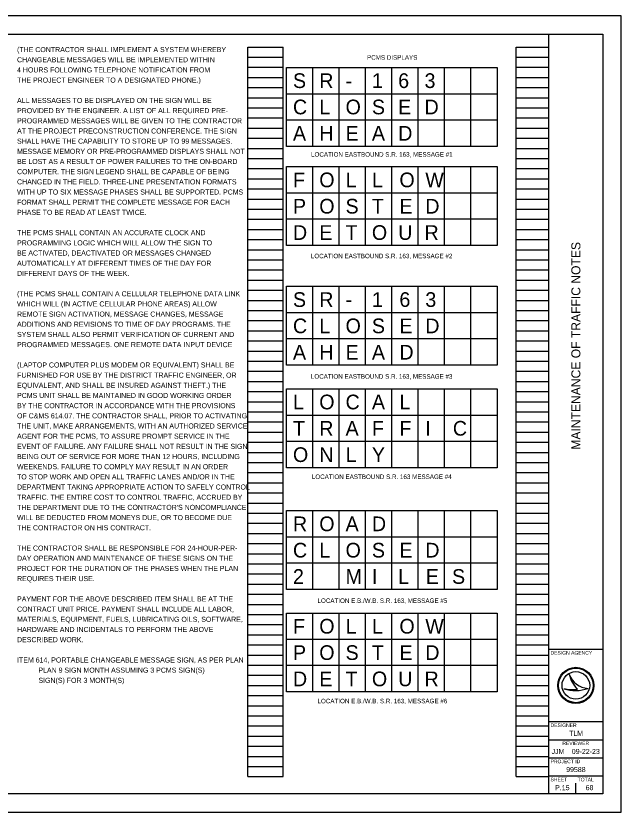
# Model space of a CAD drawing. Extents: x 0 to 34, y 0 to 22.
# Drawn here: x 17.27 to 34, y 0 to 22 of the extents above; entities that cross this region are included whole.
import ezdxf

# ---------------------------------------------------------------- set-up
doc = ezdxf.new("R2010")
doc.units = 0
for name, color, linetype in [('SH_Border', 7, 'Continuous'), ('SH_Cut_Line', 7, 'Continuous'), ('SH_Data', 7, 'Continuous'), ('SH_Text', 7, 'Continuous')]:
    doc.layers.add(name, color=color, linetype=linetype)

msp = doc.modelspace()

# ---------------------------------------------------------------- linework, layer by layer
at = {"layer": 'SH_Border'}
for p, q in [((32, 0.5), (32, 21.5)), ((32, 4.5), (33.5, 4.5)), ((32, 2.5), (33.5, 2.5)), ((32, 2), (33.5, 2)), ((32, 1.5), (33.5, 1.5)), ((32, 1), (33.5, 1))]:
    msp.add_line(p, q, dxfattribs=at)
msp.add_lwpolyline([(1.5, 21.5), (33.5, 21.5), (33.5, 0.5), (1.5, 0.5)], close=True, dxfattribs=at)
at = {"layer": 'SH_Cut_Line'}
msp.add_lwpolyline([(0, 0), (34, 0), (34, 22), (0, 22)], close=True, dxfattribs=at)
at = {"layer": 'SH_Data'}
for p, q in [((23.68, 0.98), (23.68, 21.14)), ((23.68, 21.14), (24.66, 21.14)), ((24.66, 0.98), (24.66, 21.14)), ((31.1, 0.98), (31.1, 21.14)), ((31.1, 21.14), (32, 21.14)), ((32, 0.98), (32, 21.14)), ((23.68, 20.86), (24.66, 20.86)), ((31.1, 20.86), (32, 20.86)), ((23.68, 20.58), (24.66, 20.58)), ((31.1, 20.58), (32, 20.58)), ((23.68, 20.3), (24.66, 20.3)), ((31.1, 20.3), (32, 20.3)), ((23.68, 20.02), (24.66, 20.02)), ((31.1, 20.02), (32, 20.02)), ((23.68, 19.74), (24.66, 19.74)), ((31.1, 19.74), (32, 19.74)), ((23.68, 19.46), (24.66, 19.46)), ((31.1, 19.46), (32, 19.46)), ((23.68, 19.18), (24.66, 19.18)), ((31.1, 19.18), (32, 19.18)), ((23.68, 18.9), (24.66, 18.9)), ((31.1, 18.9), (32, 18.9)), ((23.68, 18.62), (24.66, 18.62)), ((31.1, 18.62), (32, 18.62)), ((23.68, 18.34), (24.66, 18.34)), ((31.1, 18.34), (32, 18.34)), ((23.68, 18.06), (24.66, 18.06)), ((31.1, 18.06), (32, 18.06)), ((23.68, 17.78), (24.66, 17.78)), ((31.1, 17.78), (32, 17.78)), ((23.68, 17.5), (24.66, 17.5)), ((31.1, 17.5), (32, 17.5)), ((23.68, 17.22), (24.66, 17.22)), ((31.1, 17.22), (32, 17.22)), ((23.68, 16.94), (24.66, 16.94)), ((31.1, 16.94), (32, 16.94)), ((23.68, 16.66), (24.66, 16.66)), ((31.1, 16.66), (32, 16.66)), ((23.68, 16.38), (24.66, 16.38)), ((31.1, 16.38), (32, 16.38)), ((23.68, 16.1), (24.66, 16.1)), ((31.1, 16.1), (32, 16.1)), ((23.68, 15.82), (24.66, 15.82)), ((31.1, 15.82), (32, 15.82)), ((23.68, 15.54), (24.66, 15.54)), ((31.1, 15.54), (32, 15.54)), ((23.68, 15.26), (24.66, 15.26)), ((31.1, 15.26), (32, 15.26)), ((23.68, 14.98), (24.66, 14.98)), ((31.1, 14.98), (32, 14.98)), ((23.68, 14.7), (24.66, 14.7)), ((31.1, 14.7), (32, 14.7)), ((23.68, 14.42), (24.66, 14.42)), ((31.1, 14.42), (32, 14.42)), ((23.68, 14.14), (24.66, 14.14)), ((31.1, 14.14), (32, 14.14)), ((23.68, 13.86), (24.66, 13.86)), ((31.1, 13.86), (32, 13.86)), ((23.68, 13.58), (24.66, 13.58)), ((31.1, 13.58), (32, 13.58)), ((23.68, 13.3), (24.66, 13.3)), ((31.1, 13.3), (32, 13.3)), ((23.68, 13.02), (24.66, 13.02)), ((31.1, 13.02), (32, 13.02)), ((23.68, 12.74), (24.66, 12.74)), ((31.1, 12.74), (32, 12.74)), ((23.68, 12.46), (24.66, 12.46)), ((31.1, 12.46), (32, 12.46)), ((23.68, 12.18), (24.66, 12.18)), ((31.1, 12.18), (32, 12.18)), ((23.68, 11.9), (24.66, 11.9)), ((31.1, 11.9), (32, 11.9)), ((23.68, 11.62), (24.66, 11.62)), ((31.1, 11.62), (32, 11.62)), ((23.68, 11.34), (24.66, 11.34)), ((31.1, 11.34), (32, 11.34)), ((23.68, 11.06), (24.66, 11.06)), ((31.1, 11.06), (32, 11.06)), ((23.68, 10.78), (24.66, 10.78)), ((31.1, 10.78), (32, 10.78)), ((23.68, 10.5), (24.66, 10.5)), ((31.1, 10.5), (32, 10.5)), ((23.68, 10.22), (24.66, 10.22)), ((31.1, 10.22), (32, 10.22)), ((23.68, 9.94), (24.66, 9.94)), ((31.1, 9.94), (32, 9.94)), ((23.68, 9.66), (24.66, 9.66)), ((31.1, 9.66), (32, 9.66)), ((23.68, 9.38), (24.66, 9.38)), ((31.1, 9.38), (32, 9.38)), ((23.68, 9.1), (24.66, 9.1)), ((31.1, 9.1), (32, 9.1)), ((23.68, 8.82), (24.66, 8.82)), ((31.1, 8.82), (32, 8.82)), ((23.68, 8.54), (24.66, 8.54)), ((31.1, 8.54), (32, 8.54)), ((23.68, 8.26), (24.66, 8.26)), ((31.1, 8.26), (32, 8.26)), ((23.68, 7.98), (24.66, 7.98)), ((31.1, 7.98), (32, 7.98)), ((23.68, 7.7), (24.66, 7.7)), ((31.1, 7.7), (32, 7.7)), ((23.68, 7.42), (24.66, 7.42)), ((31.1, 7.42), (32, 7.42)), ((23.68, 7.14), (24.66, 7.14)), ((31.1, 7.14), (32, 7.14)), ((23.68, 6.86), (24.66, 6.86)), ((31.1, 6.86), (32, 6.86)), ((23.68, 6.58), (24.66, 6.58)), ((31.1, 6.58), (32, 6.58)), ((23.68, 6.3), (24.66, 6.3)), ((31.1, 6.3), (32, 6.3)), ((23.68, 6.02), (24.66, 6.02)), ((31.1, 6.02), (32, 6.02)), ((23.68, 5.74), (24.66, 5.74)), ((31.1, 5.74), (32, 5.74)), ((23.68, 5.46), (24.66, 5.46)), ((31.1, 5.46), (32, 5.46)), ((23.68, 5.18), (24.66, 5.18)), ((31.1, 5.18), (32, 5.18)), ((23.68, 4.9), (24.66, 4.9)), ((31.1, 4.9), (32, 4.9)), ((23.68, 4.62), (24.66, 4.62)), ((31.1, 4.62), (32, 4.62)), ((23.68, 4.34), (24.66, 4.34)), ((31.1, 4.34), (32, 4.34)), ((23.68, 4.06), (24.66, 4.06)), ((31.1, 4.06), (32, 4.06)), ((23.68, 3.78), (24.66, 3.78)), ((31.1, 3.78), (32, 3.78)), ((32.567, 3.81), (32.567, 3.81)), ((23.68, 3.5), (24.66, 3.5)), ((31.1, 3.5), (32, 3.5)), ((32.417, 3.41), (32.417, 3.41)), ((32.75, 3.5), (32.75, 3.5)), ((33.087, 3.419), (33.087, 3.419)), ((23.68, 3.22), (24.66, 3.22)), ((31.1, 3.22), (32, 3.22)), ((23.68, 2.94), (24.66, 2.94)), ((31.1, 2.94), (32, 2.94)), ((23.68, 2.66), (24.66, 2.66)), ((31.1, 2.66), (32, 2.66)), ((23.68, 2.38), (24.66, 2.38)), ((31.1, 2.38), (32, 2.38)), ((23.68, 2.1), (24.66, 2.1)), ((31.1, 2.1), (32, 2.1)), ((23.68, 1.82), (24.66, 1.82)), ((31.1, 1.82), (32, 1.82)), ((23.68, 1.54), (24.66, 1.54)), ((31.1, 1.54), (32, 1.54)), ((23.68, 1.26), (24.66, 1.26)), ((31.1, 1.26), (32, 1.26)), ((23.68, 0.98), (24.66, 0.98)), ((31.1, 0.98), (32, 0.98)), ((32.375, 0.675), (32.375, 0.675)), ((32.75, 0.5), (32.75, 0.8))]:
    msp.add_line(p, q, dxfattribs=at)
for radius in [0.5, 0.477, 0.477, 0.382]:
    msp.add_circle((32.75, 3.5), radius, dxfattribs=at)
for centre, radius, start, end in [((33.116, 3.998), 0.58, 198.9257, 198.9319), ((33.347, 3.97), 0.796, 191.6379, 191.6421), ((33.116, 3.998), 0.58, 198.9319, 267.1657), ((33.347, 3.97), 0.796, 191.6421, 226.0947), ((32.739, 4.37), 1.013, 251.4576, 290.0832), ((32.648, 4.654), 1.266, 259.4964, 259.4995), ((32.739, 4.37), 1.013, 251.4527, 251.4576), ((32.648, 4.654), 1.266, 259.4995, 276.6672)]:
    msp.add_arc(centre, radius, start, end, dxfattribs=at)
at = {"layer": 'SH_Text'}
for p, q in [((24.753, 20.578), (30.572, 20.578)), ((24.753, 18.396), (24.753, 20.578)), ((25.48, 18.396), (25.48, 20.578)), ((26.208, 18.396), (26.208, 20.578)), ((26.935, 18.396), (26.935, 20.578)), ((27.662, 18.396), (27.662, 20.578)), ((28.39, 18.396), (28.39, 20.578)), ((29.117, 18.396), (29.117, 20.578)), ((29.845, 18.396), (29.845, 20.578)), ((30.572, 20.578), (30.572, 18.396)), ((24.753, 19.85), (30.572, 19.85)), ((30.572, 19.123), (24.753, 19.123)), ((30.572, 18.396), (24.753, 18.396)), ((24.753, 17.835), (30.572, 17.835)), ((24.753, 15.653), (24.753, 17.835)), ((25.48, 15.653), (25.48, 17.835)), ((26.208, 15.653), (26.208, 17.835)), ((26.935, 15.653), (26.935, 17.835)), ((27.662, 15.653), (27.662, 17.835)), ((28.39, 15.653), (28.39, 17.835)), ((29.117, 15.653), (29.117, 17.835)), ((29.845, 15.653), (29.845, 17.835)), ((30.572, 17.835), (30.572, 15.653)), ((24.753, 17.108), (30.572, 17.108)), ((30.572, 16.38), (24.753, 16.38)), ((30.572, 15.653), (24.753, 15.653)), ((24.753, 14.529), (30.572, 14.529)), ((24.753, 12.346), (24.753, 14.529)), ((25.48, 12.346), (25.48, 14.529)), ((26.208, 12.346), (26.208, 14.529)), ((26.935, 12.346), (26.935, 14.529)), ((27.662, 12.346), (27.662, 14.529)), ((28.39, 12.346), (28.39, 14.529)), ((29.117, 12.346), (29.117, 14.529)), ((29.845, 12.346), (29.845, 14.529)), ((30.572, 14.529), (30.572, 12.346)), ((24.753, 13.801), (30.572, 13.801)), ((30.572, 13.074), (24.753, 13.074)), ((30.572, 12.346), (24.753, 12.346)), ((24.753, 11.699), (30.572, 11.699)), ((24.753, 9.516), (24.753, 11.699)), ((25.48, 9.516), (25.48, 11.699)), ((26.208, 9.516), (26.208, 11.699)), ((26.935, 9.516), (26.935, 11.699)), ((27.662, 9.516), (27.662, 11.699)), ((28.39, 9.516), (28.39, 11.699)), ((29.117, 9.516), (29.117, 11.699)), ((29.845, 9.516), (29.845, 11.699)), ((30.572, 11.699), (30.572, 9.516)), ((24.753, 10.971), (30.572, 10.971)), ((30.572, 10.244), (24.753, 10.244)), ((30.572, 9.516), (24.753, 9.516)), ((24.753, 8.331), (30.572, 8.331)), ((24.753, 6.149), (24.753, 8.331)), ((25.48, 6.149), (25.48, 8.331)), ((26.208, 6.149), (26.208, 8.331)), ((26.935, 6.149), (26.935, 8.331)), ((27.662, 6.149), (27.662, 8.331)), ((28.39, 6.149), (28.39, 8.331)), ((29.117, 6.149), (29.117, 8.331)), ((29.845, 6.149), (29.845, 8.331)), ((30.572, 8.331), (30.572, 6.149)), ((24.753, 7.604), (30.572, 7.604)), ((30.572, 6.876), (24.753, 6.876)), ((30.572, 6.149), (24.753, 6.149)), ((24.753, 5.501), (30.572, 5.501)), ((24.753, 3.319), (24.753, 5.501)), ((25.48, 3.319), (25.48, 5.501)), ((26.208, 3.319), (26.208, 5.501)), ((26.935, 3.319), (26.935, 5.501)), ((27.662, 3.319), (27.662, 5.501)), ((28.39, 3.319), (28.39, 5.501)), ((29.117, 3.319), (29.117, 5.501)), ((29.845, 3.319), (29.845, 5.501)), ((30.572, 5.501), (30.572, 3.319)), ((24.753, 4.774), (30.572, 4.774)), ((30.572, 4.046), (24.753, 4.046)), ((30.572, 3.319), (24.753, 3.319))]:
    msp.add_line(p, q, dxfattribs=at)

# ---------------------------------------------------------------- texts
at = {"layer": 'SH_Data'}
msp.add_text('MAINTENANCE OF TRAFFIC NOTES', height=0.25, rotation=90, dxfattribs=at).set_placement((32.875, 10.014))
for s, height, p in [('DESIGN AGENCY', 0.1, (32.05, 4.35)), ('DESIGNER', 0.1, (32.05, 2.35)), ('TLM', 0.14, (32.562, 2.105)), ('REVIEWER', 0.1, (32.378, 1.85)), ('JJM', 0.14, (32.078, 1.605)), ('09-22-23', 0.14, (32.638, 1.605)), ('PROJECT ID', 0.1, (32.05, 1.35)), ('99588', 0.14, (32.482, 1.105)), ('SHEET', 0.1, (32.05, 0.85)), ('TOTAL', 0.1, (32.8, 0.85)), ('P.15', 0.14, (32.178, 0.605)), ('68', 0.14, (33.021, 0.605))]:
    msp.add_text(s, height=height, dxfattribs=at).set_placement(p)
at = {"layer": 'SH_Text'}
for s, height, p in [('(THE CONTRACTOR SHALL IMPLEMENT A SYSTEM WHEREBY', 0.14, (17.303, 21)), ('PCMS DISPLAYS', 0.125, (26.978, 20.79)), ('CHANGEABLE MESSAGES WILL BE IMPLEMENTED WITHIN', 0.14, (17.303, 20.719)), ('4 HOURS FOLLOWING TELEPHONE NOTIFICATION FROM', 0.14, (17.303, 20.438)), ('THE PROJECT ENGINEER TO A DESIGNATED PHONE.)', 0.14, (17.303, 20.157)), ('S', 0.406, (24.93, 20.008)), ('R', 0.406, (25.657, 20.008)), ('1', 0.406, (27.112, 20.008)), ('6', 0.406, (27.839, 20.008)), ('3', 0.406, (28.567, 20.008)), ('-', 0.406, (26.384, 20.008)), ('ALL MESSAGES TO BE DISPLAYED ON THE SIGN WILL BE', 0.14, (17.303, 19.594)), ('C', 0.406, (24.93, 19.281)), ('L', 0.406, (25.657, 19.281)), ('O', 0.406, (26.384, 19.281)), ('S', 0.406, (27.112, 19.281)), ('E', 0.406, (27.839, 19.281)), ('D', 0.406, (28.567, 19.281)), ('PROVIDED BY THE ENGINEER. A LIST OF ALL REQUIRED PRE-', 0.14, (17.303, 19.313)), ('PROGRAMMED MESSAGES WILL BE GIVEN TO THE CONTRACTOR', 0.14, (17.303, 19.032)), ('A', 0.406, (24.93, 18.554)), ('H', 0.406, (25.657, 18.554)), ('E', 0.406, (26.384, 18.554)), ('A', 0.406, (27.112, 18.554)), ('D', 0.406, (27.839, 18.554)), ('AT THE PROJECT PRECONSTRUCTION CONFERENCE. THE SIGN', 0.14, (17.303, 18.751)), ('SHALL HAVE THE CAPABILITY TO STORE UP TO 99 MESSAGES.', 0.14, (17.303, 18.47)), ('MESSAGE MEMORY OR PRE-PROGRAMMED DISPLAYS SHALL NOT', 0.14, (17.303, 18.189)), ('BE LOST AS A RESULT OF POWER FAILURES TO THE ON-BOARD', 0.14, (17.303, 17.908)), ('LOCATION EASTBOUND S.R. 163, MESSAGE #1', 0.125, (25.43, 18.111)), ('COMPUTER. THE SIGN LEGEND SHALL BE CAPABLE OF BEING', 0.14, (17.303, 17.627)), ('F', 0.406, (24.93, 17.266)), ('O', 0.406, (25.657, 17.266)), ('L', 0.406, (26.384, 17.266)), ('L', 0.406, (27.112, 17.266)), ('O', 0.406, (27.872, 17.266)), ('W', 0.406, (28.589, 17.266)), ('CHANGED IN THE FIELD. THREE-LINE PRESENTATION FORMATS', 0.14, (17.303, 17.345)), ('WITH UP TO SIX MESSAGE PHASES SHALL BE SUPPORTED. PCMS', 0.14, (17.303, 17.064)), ('P', 0.406, (24.93, 16.539)), ('O', 0.406, (25.657, 16.539)), ('S', 0.406, (26.384, 16.539)), ('T', 0.406, (27.112, 16.539)), ('E', 0.406, (27.872, 16.539)), ('D', 0.406, (28.589, 16.539)), ('FORMAT SHALL PERMIT THE COMPLETE MESSAGE FOR EACH', 0.14, (17.303, 16.783)), ('PHASE TO BE READ AT LEAST TWICE.', 0.14, (17.303, 16.502)), ('THE PCMS SHALL CONTAIN AN ACCURATE CLOCK AND', 0.14, (17.303, 15.94)), ('D', 0.406, (24.93, 15.811)), ('E', 0.406, (25.657, 15.811)), ('T', 0.406, (26.384, 15.811)), ('O', 0.406, (27.112, 15.811)), ('U', 0.406, (27.839, 15.811)), ('R', 0.406, (28.567, 15.811)), ('PROGRAMMING LOGIC WHICH WILL ALLOW THE SIGN TO', 0.14, (17.303, 15.659)), ('BE ACTIVATED, DEACTIVATED OR MESSAGES CHANGED', 0.14, (17.303, 15.378)), ('LOCATION EASTBOUND S.R. 163, MESSAGE #2', 0.125, (25.424, 15.304)), ('AUTOMATICALLY AT DIFFERENT TIMES OF THE DAY FOR', 0.14, (17.303, 15.096)), ('DIFFERENT DAYS OF THE WEEK.', 0.14, (17.303, 14.815)), ('(THE PCMS SHALL CONTAIN A CELLULAR TELEPHONE DATA LINK', 0.14, (17.303, 14.253)), ('S', 0.406, (24.93, 13.959)), ('R', 0.406, (25.657, 13.959)), ('1', 0.406, (27.112, 13.959)), ('6', 0.406, (27.872, 13.959)), ('3', 0.406, (28.589, 13.959)), ('WHICH WILL (IN ACTIVE CELLULAR PHONE AREAS) ALLOW', 0.14, (17.303, 13.972)), ('-', 0.406, (26.384, 13.959)), ('REMOTE SIGN ACTIVATION, MESSAGE CHANGES, MESSAGE', 0.14, (17.303, 13.691)), ('C', 0.406, (24.93, 13.232)), ('O', 0.406, (26.384, 13.232)), ('S', 0.406, (27.112, 13.232)), ('ADDITIONS AND REVISIONS TO TIME OF DAY PROGRAMS. THE', 0.14, (17.303, 13.41)), ('L', 0.406, (25.657, 13.232)), ('E', 0.406, (27.872, 13.232)), ('D', 0.406, (28.589, 13.232)), ('SYSTEM SHALL ALSO PERMIT VERIFICATION OF CURRENT AND', 0.14, (17.303, 13.129)), ('PROGRAMMED MESSAGES. ONE REMOTE DATA INPUT DEVICE', 0.14, (17.303, 12.847)), ('A', 0.406, (24.93, 12.504)), ('H', 0.406, (25.657, 12.504)), ('E', 0.406, (26.384, 12.504)), ('A', 0.406, (27.112, 12.504)), ('D', 0.406, (27.872, 12.504)), ('(LAPTOP COMPUTER PLUS MODEM OR EQUIVALENT) SHALL BE', 0.14, (17.303, 12.285)), ('FURNISHED FOR USE BY THE DISTRICT TRAFFIC ENGINEER, OR', 0.14, (17.303, 12.004)), ('LOCATION EASTBOUND S.R. 163, MESSAGE #3', 0.125, (25.425, 11.976)), ('EQUIVALENT, AND SHALL BE INSURED AGAINST THEFT.) THE', 0.14, (17.303, 11.723)), ('PCMS UNIT SHALL BE MAINTAINED IN GOOD WORKING ORDER', 0.14, (17.303, 11.442)), ('L', 0.406, (24.93, 11.129)), ('O', 0.406, (25.657, 11.129)), ('C', 0.406, (26.384, 11.129)), ('A', 0.406, (27.112, 11.129)), ('L', 0.406, (27.872, 11.129)), ('BY THE CONTRACTOR IN ACCORDANCE WITH THE PROVISIONS', 0.14, (17.303, 11.161)), ('OF C&MS 614.07. THE CONTRACTOR SHALL, PRIOR TO ACTIVATING', 0.14, (17.303, 10.88)), ('T', 0.406, (24.93, 10.402)), ('R', 0.406, (25.657, 10.402)), ('A', 0.406, (26.384, 10.402)), ('F', 0.406, (27.112, 10.402)), ('F', 0.406, (27.872, 10.402)), ('I', 0.406, (28.589, 10.402)), ('C', 0.406, (29.35, 10.402)), ('THE UNIT, MAKE ARRANGEMENTS, WITH AN AUTHORIZED SERVICE', 0.14, (17.303, 10.599)), ('AGENT FOR THE PCMS, TO ASSURE PROMPT SERVICE IN THE', 0.14, (17.303, 10.317)), ('EVENT OF FAILURE. ANY FAILURE SHALL NOT RESULT IN THE SIGN', 0.14, (17.303, 10.036)), ('O', 0.406, (24.93, 9.674)), ('N', 0.406, (25.657, 9.674)), ('L', 0.406, (26.384, 9.674)), ('Y', 0.406, (27.112, 9.674)), ('BEING OUT OF SERVICE FOR MORE THAN 12 HOURS, INCLUDING', 0.14, (17.303, 9.755)), ('WEEKENDS. FAILURE TO COMPLY MAY RESULT IN AN ORDER', 0.14, (17.303, 9.474)), ('TO STOP WORK AND OPEN ALL TRAFFIC LANES AND/OR IN THE', 0.14, (17.303, 9.193)), ('LOCATION EASTBOUND S.R. 163 MESSAGE #4', 0.125, (25.452, 9.204)), ('DEPARTMENT TAKING APPROPRIATE ACTION TO SAFELY CONTROL', 0.14, (17.303, 8.912)), ('TRAFFIC. THE ENTIRE COST TO CONTROL TRAFFIC, ACCRUED BY', 0.14, (17.303, 8.631)), ("THE DEPARTMENT DUE TO THE CONTRACTOR'S NONCOMPLIANCE,", 0.14, (17.303, 8.35)), ('WILL BE DEDUCTED FROM MONEYS DUE, OR TO BECOME DUE', 0.14, (17.303, 8.068)), ('R', 0.406, (24.93, 7.762)), ('O', 0.406, (25.657, 7.762)), ('A', 0.406, (26.384, 7.762)), ('D', 0.406, (27.112, 7.762)), ('THE CONTRACTOR ON HIS CONTRACT.', 0.14, (17.303, 7.787)), ('THE CONTRACTOR SHALL BE RESPONSIBLE FOR 24-HOUR-PER-', 0.14, (17.303, 7.225)), ('C', 0.406, (24.93, 7.034)), ('L', 0.406, (25.657, 7.034)), ('O', 0.406, (26.384, 7.034)), ('S', 0.406, (27.112, 7.034)), ('E', 0.406, (27.872, 7.034)), ('D', 0.406, (28.589, 7.034)), ('DAY OPERATION AND MAINTENANCE OF THESE SIGNS ON THE', 0.14, (17.303, 6.944)), ('PROJECT FOR THE DURATION OF THE PHASES WHEN THE PLAN', 0.14, (17.303, 6.663)), ('2', 0.406, (24.93, 6.307)), ('M', 0.406, (26.384, 6.307)), ('I', 0.406, (27.112, 6.307)), ('L', 0.406, (27.839, 6.307)), ('E', 0.406, (28.6, 6.307)), ('S', 0.406, (29.327, 6.307)), ('REQUIRES THEIR USE.', 0.14, (17.303, 6.382)), ('PAYMENT FOR THE ABOVE DESCRIBED ITEM SHALL BE AT THE', 0.14, (17.303, 5.819)), ('LOCATION E.B./W.B. S.R. 163, MESSAGE #5', 0.125, (25.608, 5.779)), ('CONTRACT UNIT PRICE. PAYMENT SHALL INCLUDE ALL LABOR,', 0.14, (17.303, 5.538)), ('MATERIALS, EQUIPMENT, FUELS, LUBRICATING OILS, SOFTWARE,', 0.14, (17.303, 5.257)), ('F', 0.406, (24.93, 4.932)), ('O', 0.406, (25.657, 4.932)), ('L', 0.406, (26.384, 4.932)), ('L', 0.406, (27.112, 4.932)), ('O', 0.406, (27.872, 4.932)), ('W', 0.406, (28.589, 4.932)), ('HARDWARE AND INCIDENTALS TO PERFORM THE ABOVE', 0.14, (17.303, 4.976)), ('DESCRIBED WORK.', 0.14, (17.303, 4.695)), ('P', 0.406, (24.93, 4.204)), ('O', 0.406, (25.657, 4.204)), ('S', 0.406, (26.384, 4.204)), ('T', 0.406, (27.112, 4.204)), ('E', 0.406, (27.872, 4.204)), ('D', 0.406, (28.589, 4.204)), ('ITEM 614, PORTABLE CHANGEABLE MESSAGE SIGN, AS PER PLAN', 0.14, (17.303, 4.133)), ('           PLAN 9 SIGN MONTH ASSUMING 3 PCMS SIGN(S)', 0.14, (17.303, 3.852)), ('D', 0.406, (24.93, 3.477)), ('E', 0.406, (25.657, 3.477)), ('T', 0.406, (26.384, 3.477)), ('O', 0.406, (27.112, 3.477)), ('U', 0.406, (27.839, 3.477)), ('R', 0.406, (28.567, 3.477)), ('           SIGN(S) FOR 3 MONTH(S)', 0.14, (17.303, 3.57)), ('LOCATION E.B./W.B. S.R. 163, MESSAGE #6', 0.125, (25.608, 3.006))]:
    msp.add_text(s, height=height, dxfattribs=at).set_placement(p)

doc.saveas('drawing.dxf')
